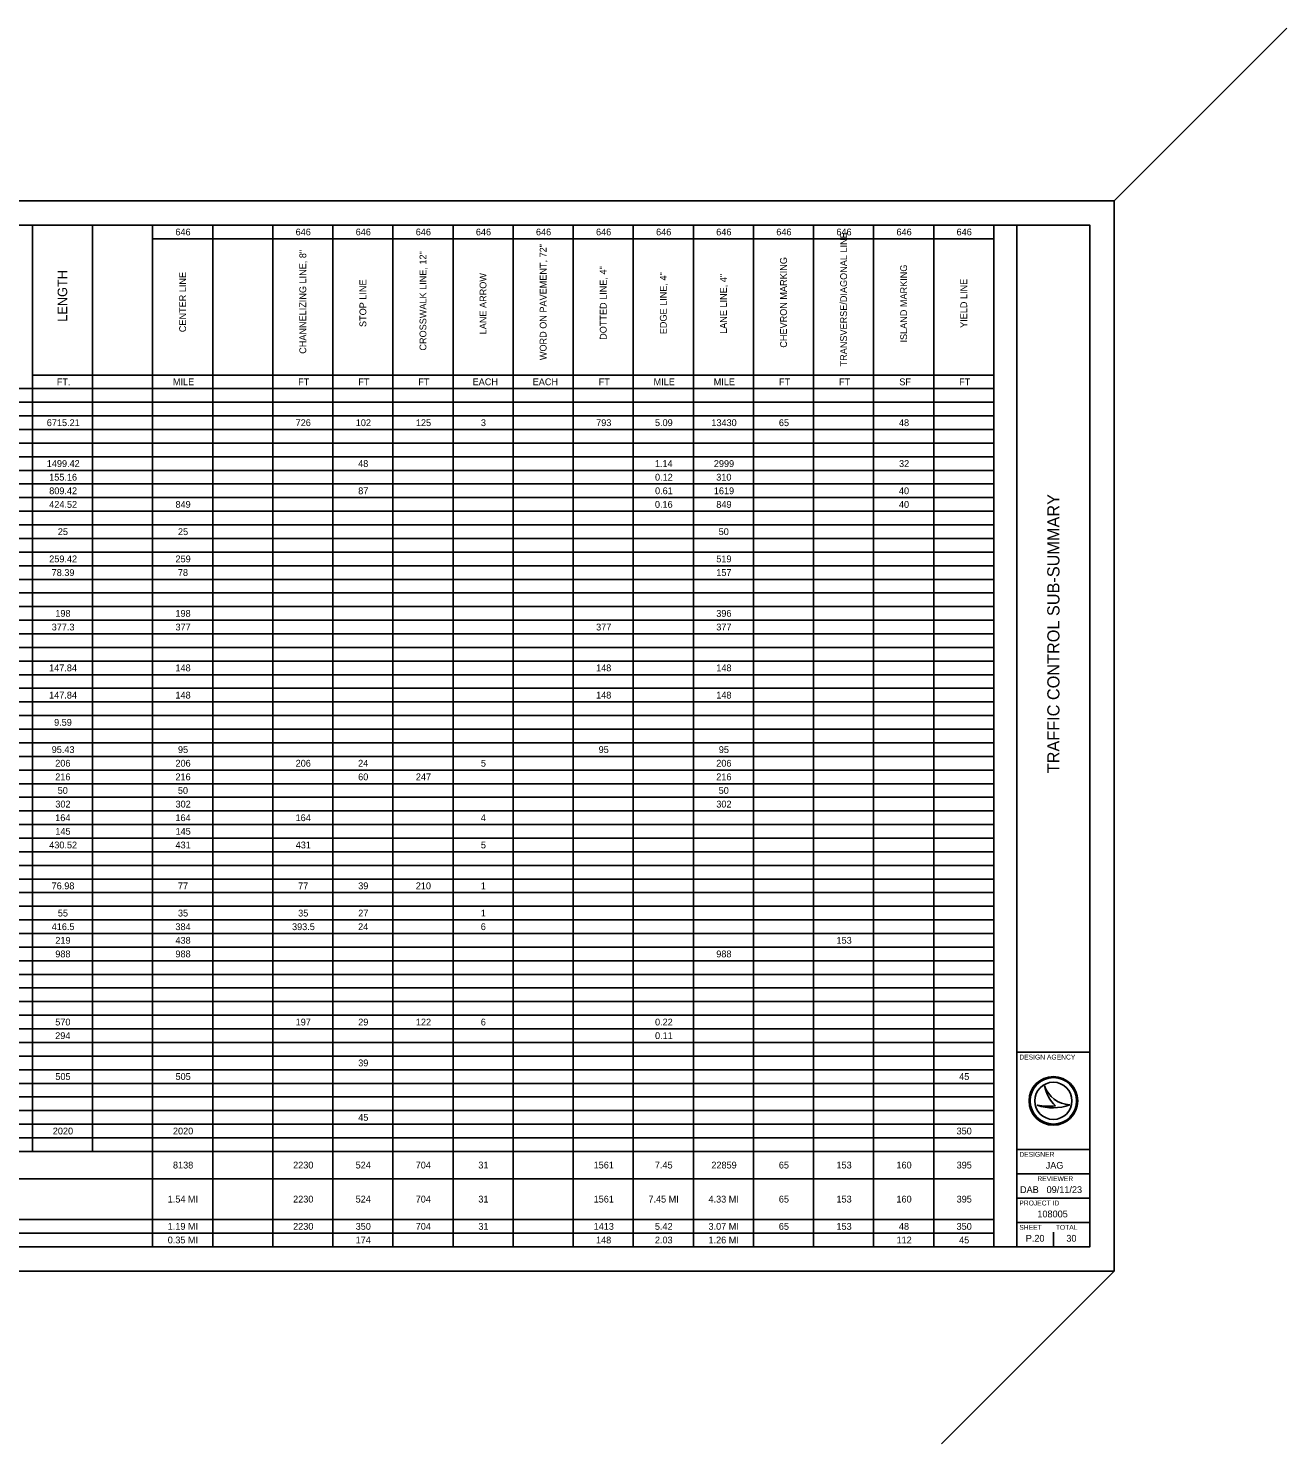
# Model space of a CAD drawing. Extents: x 768 to 809.1, y -451.7 to -422.6.
# Drawn here: x 783.25 to 809.12, y -451.72 to -422.62 of the extents above; entities that cross this region are included whole.
import ezdxf

# ---------------------------------------------------------------- set-up
doc = ezdxf.new("R2010")
doc.units = 0
for name, color, linetype in [('Level 11', 7, 'Continuous'), ('SC_Scratch1', 7, 'Continuous'), ('SH_Border', 7, 'Continuous'), ('SH_Cut_Line', 7, 'Continuous'), ('SH_Data', 7, 'Continuous')]:
    doc.layers.add(name, color=color, linetype=linetype)

msp = doc.modelspace()

# ---------------------------------------------------------------- linework, layer by layer
at = {"layer": 'Level 11'}
for p, q in [((773.069, -426.67), (803.094, -426.67)), ((783.33, -426.67), (783.33, -445.71)), ((784.565, -426.67), (784.565, -445.71)), ((785.8, -426.67), (785.8, -447.67)), ((787.036, -426.67), (787.036, -447.67)), ((788.271, -426.67), (788.271, -447.67)), ((789.506, -426.67), (789.506, -447.67)), ((790.741, -426.67), (790.741, -447.67)), ((791.977, -426.67), (791.977, -447.67)), ((793.212, -426.67), (793.212, -447.67)), ((794.447, -426.67), (794.447, -447.67)), ((795.683, -426.67), (795.683, -447.67)), ((796.918, -426.67), (796.918, -447.67)), ((798.153, -426.67), (798.153, -447.67)), ((799.389, -426.67), (799.389, -447.67)), ((800.624, -426.67), (800.624, -447.67)), ((801.859, -426.67), (801.859, -447.67)), ((803.094, -426.67), (803.094, -447.67)), ((785.8, -426.95), (803.094, -426.95)), ((783.33, -429.75), (803.094, -429.75)), ((773.069, -430.03), (803.094, -430.03)), ((773.069, -430.31), (803.094, -430.31)), ((773.069, -430.59), (803.094, -430.59)), ((773.069, -430.87), (803.094, -430.87)), ((773.069, -431.15), (803.094, -431.15)), ((773.069, -431.43), (803.094, -431.43)), ((773.069, -431.71), (803.094, -431.71)), ((773.069, -431.99), (803.094, -431.99)), ((773.069, -432.27), (803.094, -432.27)), ((773.069, -432.55), (803.094, -432.55)), ((773.069, -432.83), (803.094, -432.83)), ((773.069, -433.11), (803.094, -433.11)), ((773.069, -433.39), (803.094, -433.39)), ((773.069, -433.67), (803.094, -433.67)), ((773.069, -433.95), (803.094, -433.95)), ((773.069, -434.23), (803.094, -434.23)), ((773.069, -434.51), (803.094, -434.51)), ((773.069, -434.79), (803.094, -434.79)), ((773.069, -435.07), (803.094, -435.07)), ((773.069, -435.35), (803.094, -435.35)), ((773.069, -435.63), (803.094, -435.63)), ((773.069, -435.91), (803.094, -435.91)), ((773.069, -436.19), (803.094, -436.19)), ((773.069, -436.47), (803.094, -436.47)), ((773.069, -436.75), (803.094, -436.75)), ((773.069, -437.03), (803.094, -437.03)), ((773.069, -437.31), (803.094, -437.31)), ((773.069, -437.59), (803.094, -437.59)), ((773.069, -437.87), (803.094, -437.87)), ((773.069, -438.15), (803.094, -438.15)), ((773.069, -438.43), (803.094, -438.43)), ((773.069, -438.71), (803.094, -438.71)), ((773.069, -438.99), (803.094, -438.99)), ((773.069, -439.27), (803.094, -439.27)), ((773.069, -439.55), (803.094, -439.55)), ((773.069, -439.83), (803.094, -439.83)), ((773.069, -440.11), (803.094, -440.11)), ((773.069, -440.39), (803.094, -440.39)), ((773.069, -440.67), (803.094, -440.67)), ((773.069, -440.95), (803.094, -440.95)), ((773.069, -441.23), (803.094, -441.23)), ((773.069, -441.51), (803.094, -441.51)), ((773.069, -441.79), (803.094, -441.79)), ((773.069, -442.07), (803.094, -442.07)), ((776.083, -442.35), (783.33, -442.35)), ((783.33, -442.35), (803.094, -442.35)), ((776.083, -442.63), (783.33, -442.63)), ((783.33, -442.63), (803.094, -442.63)), ((773.069, -442.91), (803.094, -442.91)), ((773.069, -443.19), (803.094, -443.19)), ((773.069, -443.47), (803.094, -443.47)), ((773.069, -443.75), (803.094, -443.75)), ((773.069, -444.03), (803.094, -444.03)), ((773.069, -444.31), (803.094, -444.31)), ((773.069, -444.59), (803.094, -444.59)), ((773.069, -444.87), (803.094, -444.87)), ((773.069, -445.15), (803.094, -445.15)), ((773.069, -445.43), (803.094, -445.43)), ((773.069, -445.71), (803.094, -445.71)), ((773.069, -446.27), (803.094, -446.27)), ((773.069, -447.11), (803.094, -447.11)), ((773.069, -447.39), (803.094, -447.39)), ((773.069, -447.67), (803.094, -447.67))]:
    msp.add_line(p, q, dxfattribs=at)
at = {"layer": 'SC_Scratch1'}
for p, q in [((805.569, -426.17), (809.115, -422.623)), ((802.022, -451.717), (805.569, -448.17))]:
    msp.add_line(p, q, dxfattribs=at)
at = {"layer": 'SH_Border'}
for p, q in [((803.569, -447.67), (803.569, -426.67)), ((803.569, -443.67), (805.069, -443.67)), ((803.569, -445.67), (805.069, -445.67)), ((803.569, -446.17), (805.069, -446.17)), ((803.569, -446.67), (805.069, -446.67)), ((803.569, -447.17), (805.069, -447.17))]:
    msp.add_line(p, q, dxfattribs=at)
msp.add_lwpolyline([(773.069, -426.67), (805.069, -426.67), (805.069, -447.67), (773.069, -447.67)], close=True, dxfattribs=at)
at = {"layer": 'SH_Cut_Line'}
msp.add_lwpolyline([(771.569, -448.17), (805.569, -448.17), (805.569, -426.17), (771.569, -426.17)], close=True, dxfattribs=at)
at = {"layer": 'SH_Data'}
for p, q in [((804.136, -444.361), (804.136, -444.361)), ((804.136, -444.361), (804.136, -444.361)), ((803.986, -444.761), (803.986, -444.761)), ((803.986, -444.761), (803.986, -444.761)), ((804.319, -444.67), (804.319, -444.67)), ((804.656, -444.752), (804.656, -444.752)), ((804.656, -444.752), (804.656, -444.752)), ((804.319, -447.67), (804.319, -447.37)), ((803.944, -447.495), (803.944, -447.495))]:
    msp.add_line(p, q, dxfattribs=at)
for radius in [0.5, 0.5, 0.477, 0.477, 0.477, 0.477, 0.382, 0.382]:
    msp.add_circle((804.319, -444.67), radius, dxfattribs=at)
for centre, radius, start, end in [((804.684, -444.172), 0.58, 198.9257, 198.9319), ((804.915, -444.2), 0.796, 191.6379, 191.6421), ((804.684, -444.172), 0.58, 198.9319, 267.1657), ((804.915, -444.2), 0.796, 191.6421, 226.0947), ((804.684, -444.172), 0.58, 198.9257, 198.9319), ((804.915, -444.2), 0.796, 191.6379, 191.6421), ((804.684, -444.172), 0.58, 198.9319, 267.1657), ((804.915, -444.2), 0.796, 191.6421, 226.0947), ((804.308, -443.8), 1.013, 251.4576, 290.0832), ((804.308, -443.8), 1.013, 251.4576, 290.0832), ((804.216, -443.516), 1.266, 259.4964, 259.4995), ((804.308, -443.8), 1.013, 251.4527, 251.4576), ((804.216, -443.516), 1.266, 259.4995, 276.6672), ((804.216, -443.516), 1.266, 259.4964, 259.4995), ((804.308, -443.8), 1.013, 251.4527, 251.4576), ((804.216, -443.516), 1.266, 259.4995, 276.6672)]:
    msp.add_arc(centre, radius, start, end, dxfattribs=at)

# ---------------------------------------------------------------- texts
at = {"layer": 'Level 11'}
for s, p in [('646', (786.27, -426.88)), ('646', (788.741, -426.88)), ('646', (789.976, -426.88)), ('646', (791.211, -426.88)), ('646', (792.447, -426.88)), ('646', (793.682, -426.88)), ('646', (794.917, -426.88)), ('646', (796.152, -426.88)), ('646', (797.388, -426.88)), ('646', (798.623, -426.88)), ('646', (799.858, -426.88)), ('646', (801.094, -426.88)), ('646', (802.329, -426.88)), ('FT.', (783.832, -429.96)), ('MILE', (786.219, -429.96)), ('FT', (788.794, -429.96)), ('FT', (790.03, -429.96)), ('FT', (791.265, -429.96)), ('EACH', (792.38, -429.96)), ('EACH', (793.615, -429.96)), ('FT', (794.971, -429.96)), ('MILE', (796.101, -429.96)), ('MILE', (797.336, -429.96)), ('FT', (798.677, -429.96)), ('FT', (799.912, -429.96)), ('SF', (801.152, -429.96)), ('FT', (802.383, -429.96)), ('6715.21', (783.626, -430.8)), ('726', (788.742, -430.8)), ('102', (789.978, -430.8)), ('125', (791.214, -430.8)), ('3', (792.55, -430.8)), ('793', (794.92, -430.8)), ('5.09', (796.129, -430.8)), ('13430', (797.288, -430.8)), ('65', (798.676, -430.8)), ('48', (801.145, -430.8)), ('1499.42', (783.626, -431.64)), ('48', (790.027, -431.64)), ('1.14', (796.127, -431.64)), ('2999', (797.339, -431.64)), ('32', (801.146, -431.64)), ('155.16', (783.675, -431.92)), ('0.12', (796.13, -431.92)), ('310', (797.388, -431.92)), ('809.42', (783.676, -432.2)), ('87', (790.028, -432.2)), ('0.61', (796.13, -432.2)), ('1619', (797.339, -432.2)), ('40', (801.144, -432.2)), ('424.52', (783.676, -432.48)), ('849', (786.272, -432.48)), ('0.16', (796.128, -432.48)), ('849', (797.39, -432.48)), ('40', (801.144, -432.48)), ('25', (783.853, -433.04)), ('25', (786.323, -433.04)), ('50', (797.438, -433.04)), ('259.42', (783.676, -433.6)), ('259', (786.272, -433.6)), ('519', (797.39, -433.6)), ('78.39', (783.726, -433.88)), ('78', (786.321, -433.88)), ('157', (797.389, -433.88)), ('198', (783.801, -434.72)), ('198', (786.271, -434.72)), ('396', (797.389, -434.72)), ('377.3', (783.727, -435)), ('377', (786.272, -435)), ('377', (794.919, -435)), ('377', (797.389, -435)), ('147.84', (783.674, -435.84)), ('148', (786.271, -435.84)), ('148', (794.918, -435.84)), ('148', (797.389, -435.84)), ('147.84', (783.674, -436.4)), ('148', (786.271, -436.4)), ('148', (794.918, -436.4)), ('148', (797.389, -436.4)), ('9.59', (783.776, -436.96)), ('95.43', (783.727, -437.52)), ('95', (786.323, -437.52)), ('95', (794.97, -437.52)), ('95', (797.441, -437.52)), ('206', (783.8, -437.8)), ('206', (786.271, -437.8)), ('206', (788.742, -437.8)), ('24', (790.026, -437.8)), ('5', (792.55, -437.8)), ('206', (797.389, -437.8)), ('216', (783.8, -438.08)), ('216', (786.271, -438.08)), ('60', (790.027, -438.08)), ('247', (791.213, -438.08)), ('216', (797.389, -438.08)), ('50', (783.85, -438.36)), ('50', (786.321, -438.36)), ('50', (797.438, -438.36)), ('302', (783.802, -438.64)), ('302', (786.273, -438.64)), ('302', (797.39, -438.64)), ('164', (783.799, -438.92)), ('164', (786.27, -438.92)), ('164', (788.741, -438.92)), ('4', (792.547, -438.92)), ('145', (783.802, -439.2)), ('145', (786.273, -439.2)), ('430.52', (783.676, -439.48)), ('431', (786.272, -439.48)), ('431', (788.743, -439.48)), ('5', (792.55, -439.48)), ('76.98', (783.725, -440.32)), ('77', (786.322, -440.32)), ('77', (788.793, -440.32)), ('39', (790.028, -440.32)), ('210', (791.212, -440.32)), ('1', (792.549, -440.32)), ('55', (783.853, -440.88)), ('35', (786.323, -440.88)), ('35', (788.794, -440.88)), ('27', (790.028, -440.88)), ('1', (792.549, -440.88)), ('416.5', (783.727, -441.16)), ('384', (786.27, -441.16)), ('393.5', (788.668, -441.16)), ('24', (790.026, -441.16)), ('6', (792.548, -441.16)), ('219', (783.802, -441.44)), ('438', (786.271, -441.44)), ('153', (799.861, -441.44)), ('988', (783.801, -441.72)), ('988', (786.271, -441.72)), ('988', (797.389, -441.72)), ('570', (783.8, -443.12)), ('197', (788.742, -443.12)), ('29', (790.028, -443.12)), ('122', (791.214, -443.12)), ('6', (792.548, -443.12)), ('0.22', (796.13, -443.12)), ('294', (783.799, -443.4)), ('0.11', (796.13, -443.4)), ('39', (790.028, -443.96)), ('505', (783.802, -444.24)), ('505', (786.273, -444.24)), ('45', (802.382, -444.24)), ('45', (790.029, -445.08)), ('2020', (783.75, -445.36)), ('2020', (786.22, -445.36)), ('350', (802.329, -445.36)), ('8138', (786.22, -446.06)), ('2230', (788.69, -446.06)), ('524', (789.975, -446.06)), ('704', (791.21, -446.06)), ('31', (792.498, -446.06)), ('1561', (794.868, -446.06)), ('7.45', (796.127, -446.06)), ('22859', (797.288, -446.06)), ('65', (798.675, -446.06)), ('153', (799.86, -446.06)), ('160', (801.093, -446.06)), ('395', (802.33, -446.06)), ('1.54 MI', (786.112, -446.76)), ('2230', (788.69, -446.76)), ('524', (789.975, -446.76)), ('704', (791.21, -446.76)), ('31', (792.498, -446.76)), ('1561', (794.868, -446.76)), ('7.45 MI', (795.994, -446.76)), ('4.33 MI', (797.229, -446.76)), ('65', (798.675, -446.76)), ('153', (799.86, -446.76)), ('160', (801.093, -446.76)), ('395', (802.33, -446.76)), ('0.35 MI', (786.112, -447.6)), ('1.19 MI', (786.112, -447.32)), ('2230', (788.69, -447.32)), ('350', (789.976, -447.32)), ('174', (789.975, -447.6)), ('704', (791.21, -447.32)), ('31', (792.498, -447.32)), ('1413', (794.868, -447.32)), ('148', (794.917, -447.6)), ('5.42', (796.127, -447.32)), ('2.03', (796.127, -447.6)), ('3.07 MI', (797.229, -447.32)), ('1.26 MI', (797.229, -447.6)), ('65', (798.675, -447.32)), ('153', (799.86, -447.32)), ('112', (801.095, -447.6)), ('48', (801.144, -447.32)), ('350', (802.329, -447.32)), ('45', (802.381, -447.6))]:
    msp.add_text(s, height=0.14, dxfattribs=at).set_placement(p)
for s, height, p in [('WORD ON PAVEMENT, 72"', 0.14, (793.9, -429.444)), ('TRANSVERSE/DIAGONAL LINE', 0.14, (800.076, -429.573)), ('CHANNELIZING LINE, 8"', 0.14, (788.959, -429.314)), ('CROSSWALK LINE, 12"', 0.14, (791.429, -429.248)), ('CHEVRON MARKING', 0.14, (798.841, -429.188)), ('LENGTH', 0.196, (784.045, -428.656)), ('CENTER LINE', 0.14, (786.488, -428.87)), ('LANE ARROW', 0.14, (792.664, -428.913)), ('DOTTED LINE, 4"', 0.14, (795.135, -429.027)), ('EDGE LINE, 4"', 0.14, (796.37, -428.911)), ('ISLAND MARKING', 0.14, (801.311, -429.082)), ('STOP LINE', 0.14, (790.194, -428.763)), ('LANE LINE, 4"', 0.14, (797.606, -428.904)), ('YIELD LINE', 0.14, (802.547, -428.781))]:
    msp.add_text(s, height=height, rotation=90, dxfattribs=at).set_placement(p)
at = {"layer": 'SH_Data'}
msp.add_text('TRAFFIC CONTROL SUB-SUMMARY', height=0.25, rotation=90, dxfattribs=at).set_placement((804.444, -437.936))
for s, height, p in [('DESIGN AGENCY', 0.1, (803.619, -443.82)), ('DESIGNER', 0.1, (803.619, -445.82)), ('JAG', 0.14, (804.161, -446.065)), ('REVIEWER', 0.1, (803.99, -446.32)), ('DAB', 0.14, (803.633, -446.565)), ('09/11/23', 0.14, (804.18, -446.565)), ('PROJECT ID', 0.1, (803.619, -446.82)), ('108005', 0.14, (803.99, -447.065)), ('SHEET', 0.1, (803.619, -447.32)), ('P.20', 0.14, (803.751, -447.565)), ('TOTAL', 0.1, (804.369, -447.32)), ('30', 0.14, (804.586, -447.565))]:
    msp.add_text(s, height=height, dxfattribs=at).set_placement(p)

doc.saveas('drawing.dxf')
